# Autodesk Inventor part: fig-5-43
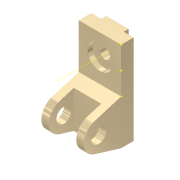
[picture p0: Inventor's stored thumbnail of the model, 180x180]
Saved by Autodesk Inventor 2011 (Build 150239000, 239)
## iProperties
Shininess: 65.0
Angle Display Precision: 2
Document Length Units: 11269
Document Angle Units: 11279
Document Time Units: 11290
Document Mass Units: 11283
Document Length Units Precision: 3
Document Angle Units Precision: 2
Created: 2001-11
Part Number: fig-5-43
Document SubType Name: Modeling
Designer: Renu Muthoo
Density: 1 g/cm^3
Density: 0.0
Volumn: 0.0
Area: 0.0
PropertySet Name: Model Information
Control State: 0
Master: False
Checked Out: False
Author: Renu Muthoo
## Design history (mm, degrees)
node "Sketch1"
sketch "Sketch2"
  geometry: L1 (33.257, 104.664)-(33.257, -75.336); L2 (33.257, -75.336)-(8.257, -75.336); L3 (8.257, -75.336)-(-45.451, -59.045); L4 (-45.451, -1.628)-(8.257, 14.664); L5 (8.257, 14.664)-(8.257, 104.664); L6 (8.257, 104.664)-(33.257, 104.664); C1 r 15 at (-36.743, -30.336); A1 r 30 centre (-36.743, -30.336) between (-45.451, -1.628) and (-45.451, -59.045)
  constraints: 12 end point, 2 centre point, 2 equal length, 2 parallel, 2 point on circle, 2 tangent, 1 coincident, 1 perpendicular, 1 vertical
  dimensions: "d0" = 180 distance of L1.start L1.end; "d1" = 30 radius of A1; "d2" = 25 distance of L5.end L1.start; "d3" = 45 distance from line of L2 A1.centre; "d4" = 70 distance from line of L1 A1.centre; "d5" = 30 diameter of C1
extrude "Extrusion1" new body sketch "Sketch2" distance "d6" = 85; taper "d7" = 0 deg
workplane "Work Plane1"
sketch "Sketch3"
  geometry: L1 (15, 62.364)-(70, 62.364); L2 (70, 62.364)-(70, -52.386); L3 (70, -52.386)-(15, -52.386); L4 (15, -52.386)-(15, 62.364); L5 (0, -45)-(0, -28.708) reference
  constraints: 8 end point, 2 parallel, 1 horizontal, 1 perpendicular
  dimensions: "d8" = 55 distance of L1.start L1.end; "d9" = 15 distance between parallel lines of L5 L4
extrude "Extrusion2" cut sketch "Sketch3" distance "d10" = 50; taper "d11" = 0 deg
sketch "Sketch4"
  geometry: L1 (0, 25)-(85, 25) reference; L2 (0, 0)-(0, 25) reference; L3 (20, 25)-(65, 25); L4 (65, 25)-(65, 35); L5 (65, 35)-(20, 35); L6 (20, 35)-(20, 25)
  constraints: 8 end point, 2 parallel, 1 horizontal, 1 perpendicular, 1 point on line
  dimensions: "d12" = 45 distance of L4.end L5.end; "d13" = 10 distance of L3.end L4.end; "d14" = 20 distance between parallel lines of L2 L6
extrude "Extrusion3" join sketch "Sketch4" stored distance "d15" = 50; taper "d16" = 0 deg
sketch "Sketch5"
  geometry: L1 (85, 0)-(85, 90) reference; L2 (0, 90)-(85, 90) reference; 1 further point
  dimensions: "d17" = 42 distance from line of L2 point (42.5, 48); "d18" = 42.5 distance from line of L1 point (42.5, 48)
hole "Hole1" sketch "Sketch5" at (42.5, 48) diameter "d19" = 20; stored, may be unused: countersink angle "d23" = 82 deg, drill point angle "d25" = 118 deg; dims "d20" = 6, "d21" = 50, "d22" = 10, "d24" = 8
workpoint "Work Point1"
workpoint "Work Point2"
workpoint "Work Point3"
workpoint "Work Point4"
workaxis "Work Axis2"
body "Solid1"
